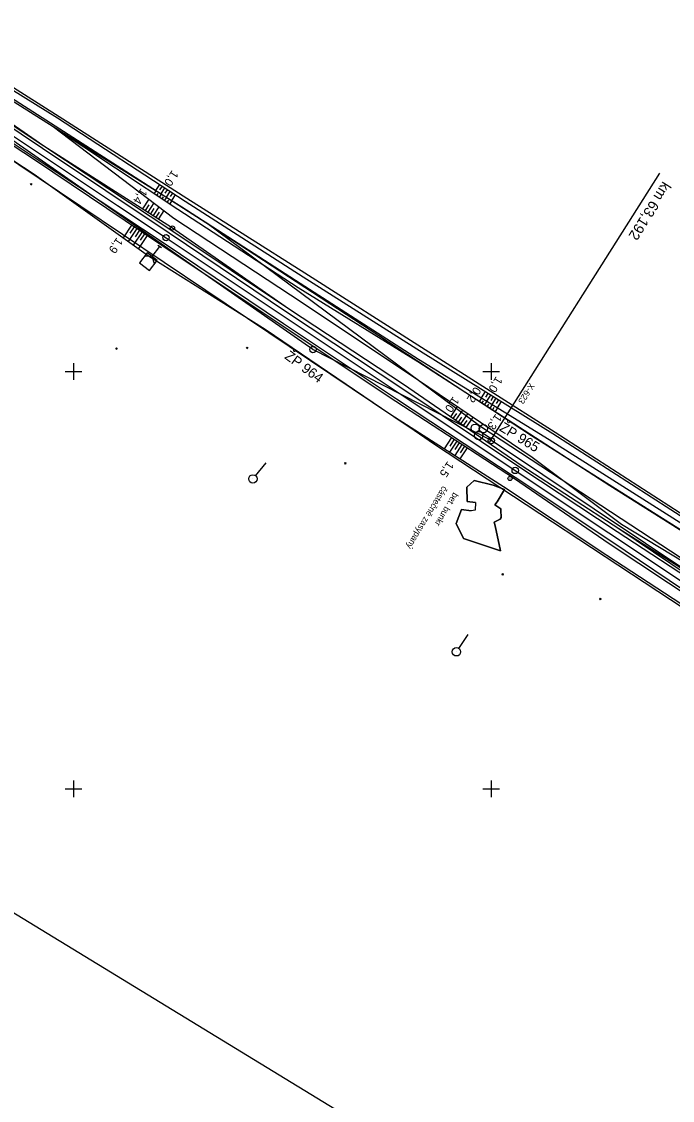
# Model space of a CAD drawing. Extents: x -804899 to -803847, y -1165742 to -1164942.
# Drawn here: x -804512.4 to -804356.6, y -1165474.6 to -1165216.2 of the extents above; entities that cross this region are included whole.
import ezdxf

# ---------------------------------------------------------------- set-up
doc = ezdxf.new("R2010")
doc.units = 0
for name, color, linetype in [('0381KM061-064P - Vrstva 1', 7, 'Continuous'), ('0381KM061-064P - Vrstva 23', 7, 'Continuous'), ('0381KM061-064P - Vrstva 36', 7, 'Continuous'), ('0381KM061-064P - Vrstva 4', 7, 'Continuous'), ('0381KM061-064P - Vrstva 48', 7, 'Continuous'), ('0381KM061-064P - Vrstva 49', 7, 'Continuous'), ('0381KM061-064P - Vrstva 51', 7, 'Continuous'), ('0381KM061-064P - Vrstva 55', 7, 'Continuous'), ('0381KM061-064P - Vrstva 7', 7, 'Continuous'), ('0381KM061-064P - Vrstva 8', 7, 'Continuous'), ('formát', 7, 'Continuous'), ('hran DP - hran DP', 7, 'Continuous'), ('krizky_1000 - Vrstva 1', 7, 'Continuous'), ('vyt_sit - polygon', 7, 'Continuous'), ('vyt_sit - stávající', 7, 'Continuous')]:
    doc.layers.add(name, color=color, linetype=linetype)

msp = doc.modelspace()

# ---------------------------------------------------------------- linework, layer by layer
at = {"layer": '0381KM061-064P - Vrstva 1'}
msp.add_lwpolyline([(-804619.36, -1165173.74), (-804594.78, -1165190.05), (-804577, -1165201.91), (-804561.16, -1165212.47), (-804538.32, -1165227.67), (-804515.3, -1165243.02), (-804489.41, -1165260.27), (-804477.81, -1165268), (-804447.6, -1165288.14), (-804422.03, -1165305.2), (-804398.19, -1165321.09), (-804394.24, -1165323.73), (-804371.85, -1165338.65), (-804349.9, -1165353.29), (-804326.64, -1165368.8), (-804303.84, -1165384.01), (-804280.33, -1165399.7), (-804257.04, -1165415.23), (-804233.85, -1165430.69)], dxfattribs=at)
at = {"layer": '0381KM061-064P - Vrstva 23'}
msp.add_lwpolyline([(-804404.03, -1165326.13), (-804405.8, -1165327.74), (-804405.76, -1165331.16), (-804403.73, -1165331.39), (-804403.83, -1165333.25), (-804404.81, -1165333.4), (-804407.08, -1165333.06), (-804408.38, -1165336.47), (-804406.6, -1165340), (-804397.73, -1165342.97), (-804399.04, -1165336.98), (-804399.28, -1165336.09), (-804397.81, -1165335.38), (-804397.64, -1165335), (-804397.65, -1165333.2), (-804397.7, -1165332.91), (-804399.15, -1165331.95), (-804398.58, -1165331.24), (-804396.84, -1165328.29), (-804399.49, -1165327.23), (-804404.03, -1165326.13)], dxfattribs=at)
at = {"layer": '0381KM061-064P - Vrstva 36'}
for p, q in [((-804456.41, -1165324.98), (-804453.88, -1165321.88)), ((-804457.04, -1165325.75), (-804457.04, -1165325.75)), ((-804407.75, -1165366.33), (-804405.5, -1165363.02)), ((-804408.31, -1165367.16), (-804408.31, -1165367.16))]:
    msp.add_line(p, q, dxfattribs=at)
for centre in [(-804457.04, -1165325.75), (-804408.31, -1165367.16)]:
    msp.add_circle(centre, 1, dxfattribs=at)
at = {"layer": '0381KM061-064P - Vrstva 4'}
for points in [[(-804755.73, -1165115.93), (-804748.17, -1165116.91), (-804721.25, -1165123.25), (-804698.66, -1165130.22), (-804681.33, -1165136.99), (-804671.47, -1165141.65), (-804648.84, -1165153.36), (-804638.11, -1165160.03), (-804624.48, -1165168.7), (-804602.56, -1165183.07), (-804574.47, -1165201.72), (-804542.72, -1165222.84), (-804507.36, -1165246.55), (-804477.08, -1165266.82), (-804448.75, -1165285.88), (-804421.18, -1165304.15), (-804392.89, -1165323.09), (-804369.85, -1165338.37), (-804348.86, -1165352.04), (-804325.13, -1165367.98), (-804299.32, -1165385.27), (-804266.05, -1165407.31), (-804234.28, -1165428.6)], [(-804755.73, -1165115.93), (-804748.03, -1165116.49), (-804721.05, -1165122.36), (-804698.44, -1165129.77), (-804680.98, -1165136.5), (-804671.21, -1165140.89), (-804648.42, -1165152.46), (-804637.55, -1165159.43), (-804624.04, -1165168.29), (-804602.25, -1165182.38), (-804573.74, -1165201.2), (-804542.46, -1165222.56), (-804507.06, -1165246.03), (-804476.47, -1165266.24), (-804448.31, -1165285.08), (-804421.02, -1165303.1), (-804392.59, -1165322.59), (-804369.41, -1165337.65), (-804348.68, -1165351.59), (-804324.76, -1165367.42), (-804298.9, -1165384.42), (-804265.65, -1165406.5), (-804234.05, -1165428.04)], [(-804626.64, -1165171.43), (-804605.18, -1165186.34), (-804576.91, -1165204.69), (-804544.69, -1165226.09), (-804509.35, -1165249.3), (-804478.87, -1165269.77), (-804450.06, -1165288.98), (-804422.82, -1165307.11), (-804394.42, -1165325.66), (-804371.77, -1165341.24), (-804350.46, -1165355.38), (-804326.73, -1165371.34), (-804301.47, -1165388.34), (-804268.3, -1165410.72), (-804235.74, -1165432.01)], [(-804576.36, -1165204.15), (-804544.19, -1165225.52), (-804508.95, -1165249), (-804478.52, -1165269.18), (-804449.67, -1165288.56), (-804422.62, -1165306.58), (-804394.22, -1165325.33), (-804371.37, -1165340.61), (-804350.54, -1165354.66), (-804326.31, -1165370.81), (-804300.9, -1165387.72), (-804267.8, -1165409.92), (-804235.52, -1165431.44)]]:
    msp.add_lwpolyline(points, dxfattribs=at)
at = {"layer": '0381KM061-064P - Vrstva 48'}
for p, q in [((-804480.29, -1165256.71), (-804479.34, -1165255.26)), ((-804479.28, -1165256.53), (-804478.71, -1165255.67)), ((-804479.02, -1165257.51), (-804478.08, -1165256.08)), ((-804478.01, -1165257.34), (-804477.46, -1165256.49)), ((-804481.97, -1165258.76), (-804483.45, -1165261.08)), ((-804480.25, -1165256.74), (-804480.67, -1165257.37)), ((-804479.78, -1165257.4), (-804480.04, -1165257.79)), ((-804478.97, -1165257.53), (-804479.42, -1165258.2)), ((-804478.52, -1165258.2), (-804478.79, -1165258.61)), ((-804477.7, -1165258.33), (-804478.16, -1165259.03)), ((-804477.74, -1165258.3), (-804476.83, -1165256.9)), ((-804477.25, -1165259.01), (-804477.54, -1165259.44)), ((-804476.43, -1165259.12), (-804476.91, -1165259.86)), ((-804476.74, -1165258.14), (-804476.2, -1165257.3)), ((-804476.47, -1165259.09), (-804475.57, -1165257.71)), ((-804481.95, -1165260.12), (-804482.82, -1165261.48)), ((-804480.77, -1165259.67), (-804482.18, -1165261.89)), ((-804480.72, -1165260.99), (-804481.55, -1165262.29)), ((-804479.57, -1165260.57), (-804480.92, -1165262.69)), ((-804478.37, -1165261.48), (-804479.66, -1165263.5)), ((-804479.5, -1165261.86), (-804480.29, -1165263.1)), ((-804486.06, -1165264.95), (-804488.11, -1165268)), ((-804484.82, -1165265.78), (-804486.89, -1165268.87)), ((-804485.44, -1165265.36), (-804486.47, -1165266.9)), ((-804483.57, -1165266.62), (-804485.67, -1165269.74)), ((-804484.19, -1165266.2), (-804485.24, -1165267.75)), ((-804482.32, -1165267.45), (-804484.45, -1165270.61)), ((-804482.95, -1165267.04), (-804484, -1165268.61)), ((-804402.3, -1165306.36), (-804401.37, -1165304.86)), ((-804401.29, -1165306.16), (-804400.73, -1165305.26)), ((-804401.02, -1165307.14), (-804400.09, -1165305.66)), ((-804402.31, -1165306.35), (-804402.82, -1165307.15)), ((-804401.88, -1165307.07), (-804402.19, -1165307.55)), ((-804401.03, -1165307.14), (-804401.56, -1165307.96)), ((-804400.6, -1165307.87), (-804400.93, -1165308.37)), ((-804399.75, -1165307.92), (-804400.3, -1165308.78)), ((-804400.01, -1165306.94), (-804399.46, -1165306.05)), ((-804399.74, -1165307.93), (-804398.82, -1165306.45)), ((-804398.73, -1165307.73), (-804398.18, -1165306.84)), ((-804398.46, -1165308.71), (-804397.55, -1165307.24)), ((-804409.69, -1165310.87), (-804408.04, -1165308.45)), ((-804409.07, -1165311.29), (-804408.24, -1165310.08)), ((-804408.45, -1165311.72), (-804406.79, -1165309.3)), ((-804407.22, -1165312.57), (-804405.55, -1165310.14)), ((-804399.33, -1165308.66), (-804399.67, -1165309.19)), ((-804398.47, -1165308.71), (-804399.04, -1165309.59)), ((-804407.84, -1165312.14), (-804407, -1165310.93)), ((-804406.6, -1165312.99), (-804405.76, -1165311.77)), ((-804405.98, -1165313.41), (-804404.31, -1165310.98)), ((-804411.18, -1165318.55), (-804409.42, -1165315.86)), ((-804409.92, -1165319.36), (-804408.16, -1165316.68)), ((-804409.84, -1165317.89), (-804408.79, -1165316.27)), ((-804408.65, -1165320.17), (-804406.91, -1165317.5)), ((-804408.58, -1165318.7), (-804407.54, -1165317.09)), ((-804407.39, -1165320.98), (-804405.65, -1165318.32)), ((-804407.32, -1165319.51), (-804406.28, -1165317.91))]:
    msp.add_line(p, q, dxfattribs=at)
at = {"layer": '0381KM061-064P - Vrstva 49'}
for p, q in [((-804509.94, -1165255.38), (-804510.3, -1165255.03)), ((-804509.94, -1165255.03), (-804510.3, -1165255.38)), ((-804489.49, -1165294.74), (-804489.84, -1165294.38)), ((-804489.49, -1165294.38), (-804489.84, -1165294.74)), ((-804458.23, -1165294.57), (-804458.58, -1165294.21)), ((-804458.23, -1165294.21), (-804458.58, -1165294.57)), ((-804434.74, -1165322.21), (-804435.09, -1165321.86)), ((-804434.74, -1165321.86), (-804435.09, -1165322.21)), ((-804397.06, -1165348.83), (-804397.41, -1165348.47)), ((-804397.06, -1165348.47), (-804397.41, -1165348.83)), ((-804373.68, -1165354.74), (-804374.04, -1165354.39)), ((-804373.68, -1165354.39), (-804374.04, -1165354.74))]:
    msp.add_line(p, q, dxfattribs=at)
for points in [[(-804668.09, -1165135.13), (-804646.08, -1165148.91), (-804635.34, -1165155.79), (-804621.98, -1165164.4), (-804599.68, -1165178.86), (-804570.23, -1165197.63), (-804539.04, -1165217.4), (-804503.79, -1165239.32), (-804473.21, -1165259.25), (-804445.02, -1165277.37), (-804416.3, -1165295.6), (-804385.23, -1165314.87), (-804342.84, -1165342.16), (-804322.16, -1165355.5), (-804292.15, -1165374.6), (-804262.58, -1165393.44), (-804234.25, -1165411.43)], [(-804668.53, -1165136.56), (-804646.51, -1165150.38), (-804635.75, -1165157.19), (-804622.88, -1165165.28), (-804600.74, -1165180), (-804571.06, -1165199.05), (-804539.91, -1165219.23), (-804504.85, -1165241.38), (-804474.07, -1165260.59), (-804445.75, -1165278.86), (-804417.38, -1165297.08), (-804386.13, -1165316.29), (-804343.68, -1165343.22), (-804323.05, -1165356.81), (-804293.41, -1165375.48), (-804263.45, -1165394.43), (-804234.68, -1165412.78)], [(-804651.73, -1165158.22), (-804641.24, -1165165.82), (-804629.21, -1165174.28), (-804606.38, -1165188.59), (-804578.69, -1165207.38), (-804546.55, -1165228.41), (-804509.4, -1165252.77), (-804482.02, -1165272.35), (-804454.07, -1165289.87), (-804424.02, -1165310.32)], [(-804621.79, -1165169), (-804602.1, -1165181.9), (-804573.29, -1165200.8), (-804541.65, -1165222.05), (-804507.06, -1165246.03), (-804476.55, -1165265.48), (-804448.31, -1165285.08)], [(-804576.91, -1165204.69), (-804544.69, -1165226.09), (-804509.35, -1165249.3), (-804478.87, -1165269.77), (-804450.06, -1165288.98), (-804422.82, -1165307.11), (-804394.42, -1165325.66), (-804371.77, -1165341.24), (-804350.46, -1165355.38), (-804326.73, -1165371.34), (-804301.47, -1165388.34), (-804268.3, -1165410.72), (-804235.74, -1165432.01)], [(-804504.85, -1165241.38), (-804475.98, -1165263.3)], [(-804504.85, -1165241.38), (-804474.97, -1165261.14)], [(-804474.97, -1165261.14), (-804446.16, -1165279.93), (-804417.55, -1165297.62), (-804371.56, -1165327.37), (-804344.89, -1165344.14), (-804323.3, -1165357.63), (-804293.83, -1165376.15), (-804263.84, -1165395.04), (-804235.23, -1165413.58)], [(-804475.98, -1165263.3), (-804448.01, -1165281.64), (-804419.88, -1165300.43), (-804390.2, -1165320.54), (-804368.79, -1165336.61), (-804347.55, -1165349.48), (-804323.92, -1165365.2), (-804298.45, -1165381.67), (-804264.49, -1165403.75), (-804232.5, -1165426.01)], [(-804448.31, -1165285.08), (-804421.02, -1165303.1), (-804392.59, -1165322.59), (-804369.41, -1165337.65)], [(-804424.02, -1165310.32), (-804397.08, -1165327.6), (-804372.3, -1165344.03), (-804352.55, -1165356.96), (-804329.59, -1165372.88)], [(-804403.73, -1165331.39), (-804405.76, -1165331.16), (-804405.8, -1165327.74), (-804404.03, -1165326.13), (-804399.49, -1165327.23), (-804396.84, -1165328.29), (-804398.58, -1165331.24)], [(-804403.73, -1165331.39), (-804403.83, -1165333.25), (-804404.81, -1165333.4)], [(-804398.58, -1165331.24), (-804399.15, -1165331.95), (-804397.7, -1165332.91), (-804397.65, -1165333.2), (-804397.64, -1165335), (-804397.81, -1165335.38), (-804399.28, -1165336.09), (-804399.04, -1165336.98)], [(-804399.04, -1165336.98), (-804397.73, -1165342.97), (-804406.6, -1165340), (-804408.38, -1165336.47), (-804407.08, -1165333.06), (-804404.81, -1165333.4)], [(-804369.41, -1165337.65), (-804350.13, -1165349.85)]]:
    msp.add_lwpolyline(points, dxfattribs=at)
at = {"layer": '0381KM061-064P - Vrstva 51'}
msp.add_lwpolyline([(-804728.9, -1165105.9), (-804711.54, -1165108.67), (-804704.35, -1165111.8), (-804683.69, -1165124.09), (-804676.95, -1165128.43), (-804667.36, -1165134.41), (-804645.71, -1165148.3), (-804634.7, -1165155.23), (-804621.63, -1165163.62), (-804599.19, -1165178.23), (-804569.67, -1165197.16), (-804538.42, -1165216.77), (-804503.41, -1165238.94), (-804472.82, -1165258.55), (-804444.57, -1165276.4), (-804415.82, -1165294.73), (-804384.7, -1165314.57), (-804342.59, -1165341.72), (-804321.8, -1165355.02), (-804291.77, -1165374.22), (-804262.45, -1165392.96)], dxfattribs=at)
at = {"layer": '0381KM061-064P - Vrstva 55'}
msp.add_lwpolyline([(-804468.27, -1165264.32), (-804426.86, -1165291.43), (-804390.35, -1165315.35), (-804348.41, -1165341.86), (-804327.45, -1165354.94), (-804302.94, -1165371.26), (-804261.01, -1165397.26), (-804213.5, -1165427.44), (-804191.69, -1165441.88), (-804177.28, -1165451.4), (-804169.73, -1165458.18), (-804172.29, -1165470.42), (-804193.11, -1165453.43), (-804217.51, -1165435.77), (-804323.51, -1165365.07), (-804402.46, -1165313.29)], close=True, dxfattribs=at)
at = {"layer": '0381KM061-064P - Vrstva 7'}
for p, q in [((-804476.35, -1165265.63), (-804476.26, -1165265.69)), ((-804481.17, -1165272.51), (-804479.35, -1165270.13)), ((-804478.95, -1165270.43), (-804479.75, -1165269.83)), ((-804395.51, -1165325.63), (-804395.43, -1165325.69))]:
    msp.add_line(p, q, dxfattribs=at)
for points in [[(-804481.17, -1165272.51), (-804482.36, -1165271.6), (-804484.18, -1165273.99), (-804481.8, -1165275.81), (-804479.98, -1165273.42), (-804481.17, -1165272.51)], [(-804480.59, -1165274.22), (-804481.17, -1165272.51), (-804482.97, -1165272.4)]]:
    msp.add_lwpolyline(points, dxfattribs=at)
for centre, radius in [((-804476.3, -1165265.66), 0.5), ((-804477.81, -1165268), 0.75), ((-804394.24, -1165323.73), 0.75), ((-804395.47, -1165325.66), 0.5)]:
    msp.add_circle(centre, radius, dxfattribs=at)
at = {"layer": '0381KM061-064P - Vrstva 8'}
for p, q in [((-804399.91, -1165316.21), (-804359.62, -1165252.51)), ((-804399.91, -1165316.21), (-804402.41, -1165314.55)), ((-804400.33, -1165316.84), (-804399.49, -1165315.59))]:
    msp.add_line(p, q, dxfattribs=at)
for centre in [(-804403.82, -1165313.61), (-804401.85, -1165313.72), (-804402.96, -1165315.38)]:
    msp.add_circle(centre, 1, dxfattribs=at)
at = {"layer": 'formát'}
msp.add_line((-804360.64, -1165523.44), (-804898.57, -1165195.52), dxfattribs=at)
at = {"layer": 'hran DP - hran DP'}
for p, q in [((-804418.46, -1165314.18), (-804552.85, -1165223.84)), ((-804519.76, -1165231.32), (-804468.27, -1165264.32)), ((-804468.27, -1165264.32), (-804426.86, -1165291.43)), ((-804426.86, -1165291.43), (-804390.35, -1165315.35)), ((-804413.53, -1165317.49), (-804418.46, -1165314.18)), ((-804390.35, -1165315.35), (-804348.41, -1165341.86)), ((-804272.3, -1165410.7), (-804413.53, -1165317.49))]:
    msp.add_line(p, q, dxfattribs=at)
at = {"layer": 'krizky_1000 - Vrstva 1'}
for points in [[(-804502, -1165300), (-804498, -1165300)], [(-804500, -1165298), (-804500, -1165302)], [(-804402, -1165300), (-804398, -1165300)], [(-804400, -1165298), (-804400, -1165302)], [(-804500, -1165398), (-804500, -1165402)], [(-804400, -1165398), (-804400, -1165402)], [(-804502, -1165400), (-804498, -1165400)], [(-804402, -1165400), (-804398, -1165400)]]:
    msp.add_lwpolyline(points, dxfattribs=at)
at = {"layer": 'vyt_sit - polygon'}
for p, q in [((-804442.66, -1165294.77), (-804641.93, -1165155.93)), ((-804399.95, -1165316.58), (-804442.66, -1165294.77)), ((-804220.83, -1165436.35), (-804399.95, -1165316.58))]:
    msp.add_line(p, q, dxfattribs=at)
at = {"layer": 'vyt_sit - stávající'}
for p, q in [((-804442.7, -1165294.74), (-804442.61, -1165294.8)), ((-804399.99, -1165316.55), (-804399.91, -1165316.61))]:
    msp.add_line(p, q, dxfattribs=at)
for centre in [(-804442.66, -1165294.77), (-804399.95, -1165316.58)]:
    msp.add_circle(centre, 0.756, dxfattribs=at)

# ---------------------------------------------------------------- texts
at = {"layer": '0381KM061-064P - Vrstva 23'}
for s, p in [('částečně zasypaný', (-804411.6, -1165327.33)), ('bet. bunkr', (-804409.02, -1165328.87))]:
    msp.add_text(s, height=1.5, rotation=239.0639, dxfattribs=at).set_placement(p)
at = {"layer": '0381KM061-064P - Vrstva 48'}
for s, rotation, p in [('1,0', 236.9037, (-804476.36, -1165251.68)), ('1,4', 237.4781, (-804483.81, -1165256.02)), ('1,9', 236.1009, (-804489.6, -1165267.8)), ('1,0', 238.1936, (-804398.79, -1165301.06)), ('0,2', 237.1025, (-804403.93, -1165303.54)), ('1,0', 235.8765, (-804409.09, -1165305.87)), ('1,3', 235.5742, (-804398.89, -1165310.02)), ('1,5', 236.8458, (-804410.41, -1165321.38))]:
    msp.add_text(s, height=2, rotation=rotation, dxfattribs=at).set_placement(p)
at = {"layer": '0381KM061-064P - Vrstva 8'}
for s, height, rotation, p in [('km 63,192', 2.5, 237.6925, (-804358.88, -1165254.34)), ('X-623', 1.5, 237.6921, (-804390.75, -1165302.64))]:
    msp.add_text(s, height=height, rotation=rotation, dxfattribs=at).set_placement(p)
at = {"layer": 'vyt_sit - stávající'}
for s, rotation, p in [('ŽP 964', 323.5611, (-804449.64, -1165296.77)), ('ŽP 965', 328.5611, (-804398.21, -1165314.06))]:
    msp.add_text(s, height=2.4, rotation=rotation, dxfattribs=at).set_placement(p)

doc.saveas('drawing.dxf')
